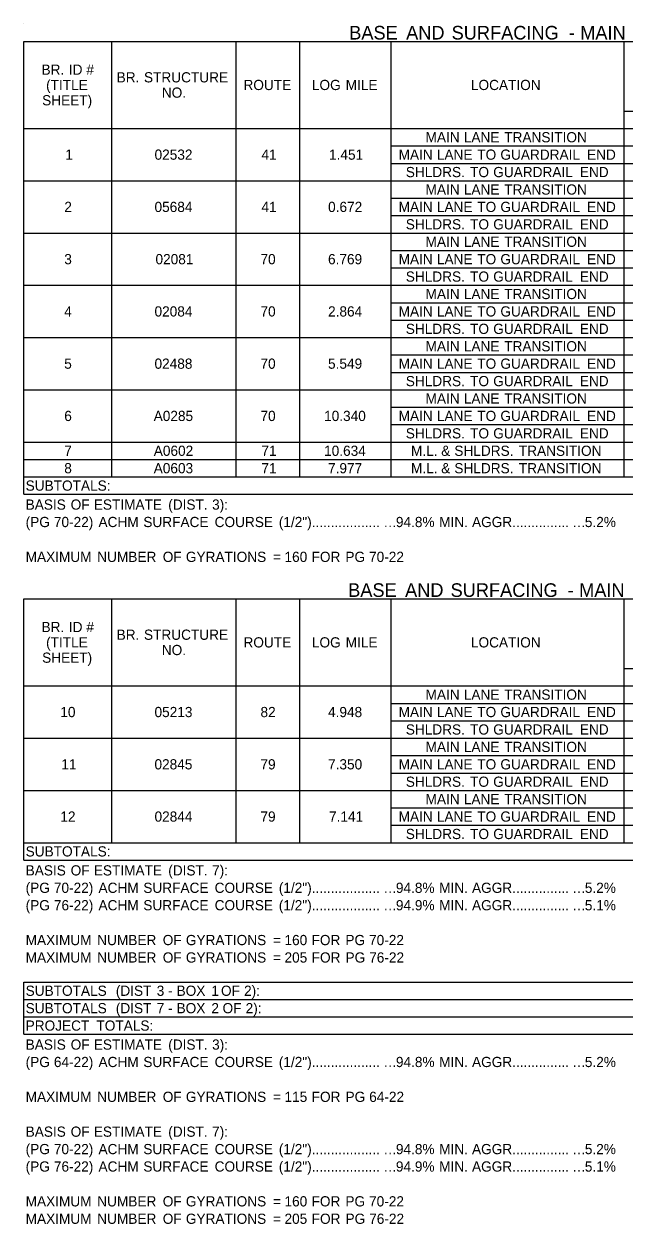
# Model space of a CAD drawing. Extents: x 544478 to 1930787, y -1948294 to 596640.
# Drawn here: x 548362 to 548715, y -1946874 to -1946169 of the extents above; entities that cross this region are included whole.
import ezdxf

# ---------------------------------------------------------------- set-up
doc = ezdxf.new("R2010")
doc.units = 0
doc.layers.add('Default', color=7, linetype='Continuous')

msp = doc.modelspace()

# ---------------------------------------------------------------- linework, layer by layer
at = {"layer": 'Default'}
for p, q in [((548361.91, -1946168.6), (548361.91, -1946168.6)), ((548361.91, -1946178.84), (549135.09, -1946178.84)), ((548361.91, -1946178.84), (549135.09, -1946178.84)), ((548361.91, -1946445.02), (548361.91, -1946178.84)), ((548413.59, -1946230.03), (548413.59, -1946178.84)), ((548486.71, -1946230.03), (548486.71, -1946178.84)), ((548524.25, -1946230.03), (548524.25, -1946178.84)), ((548577.88, -1946434.78), (548577.88, -1946178.84)), ((548714.86, -1946434.78), (548714.86, -1946178.84)), ((548714.86, -1946219.79), (548776.78, -1946219.79)), ((548714.86, -1946219.79), (548836.25, -1946219.79)), ((548361.91, -1946230.03), (549135.09, -1946230.03)), ((548413.59, -1946434.78), (548413.59, -1946230.03)), ((548486.71, -1946434.78), (548486.71, -1946230.03)), ((548524.25, -1946434.78), (548524.25, -1946230.03)), ((548577.88, -1946240.27), (549135.09, -1946240.27)), ((548577.88, -1946250.5), (548714.86, -1946250.5)), ((548577.88, -1946250.5), (549135.09, -1946250.5)), ((548361.91, -1946260.74), (549135.09, -1946260.74)), ((548577.88, -1946270.98), (549135.09, -1946270.98)), ((548577.88, -1946281.22), (548714.86, -1946281.22)), ((548577.88, -1946281.22), (549135.09, -1946281.22)), ((548361.91, -1946291.45), (549036.61, -1946291.45)), ((548714.86, -1946291.45), (548836.25, -1946291.45)), ((548577.88, -1946301.69), (549135.09, -1946301.69)), ((548577.88, -1946311.93), (548714.86, -1946311.93)), ((548577.88, -1946311.93), (549135.09, -1946311.93)), ((548361.91, -1946322.17), (549135.09, -1946322.17)), ((548577.88, -1946332.4), (549135.09, -1946332.4)), ((548577.88, -1946342.64), (548714.86, -1946342.64)), ((548577.88, -1946342.64), (549135.09, -1946342.64)), ((548361.91, -1946352.88), (549036.61, -1946352.88)), ((548714.86, -1946352.88), (548836.25, -1946352.88)), ((548577.88, -1946363.12), (549135.09, -1946363.12)), ((548577.88, -1946373.35), (548714.86, -1946373.35)), ((548577.88, -1946373.35), (549135.09, -1946373.35)), ((548361.91, -1946383.59), (549135.09, -1946383.59)), ((548577.88, -1946393.83), (549135.09, -1946393.83)), ((548577.88, -1946404.07), (548714.86, -1946404.07)), ((548577.88, -1946404.07), (549135.09, -1946404.07)), ((548361.91, -1946414.3), (549135.09, -1946414.3)), ((548577.88, -1946414.3), (549135.09, -1946414.3)), ((548361.91, -1946424.54), (548524.25, -1946424.54)), ((548524.25, -1946424.54), (549135.09, -1946424.54)), ((548361.91, -1946434.78), (549135.09, -1946434.78)), ((548361.91, -1946445.02), (549135.09, -1946445.02)), ((548361.91, -1946506.44), (549135.09, -1946506.44)), ((548361.91, -1946506.44), (549135.09, -1946506.44)), ((548361.91, -1946660), (548361.91, -1946506.44)), ((548413.59, -1946557.63), (548413.59, -1946506.44)), ((548486.71, -1946557.63), (548486.71, -1946506.44)), ((548524.25, -1946557.63), (548524.25, -1946506.44)), ((548577.88, -1946649.77), (548577.88, -1946506.44)), ((548714.86, -1946649.77), (548714.86, -1946506.44)), ((548714.86, -1946547.39), (548776.78, -1946547.39)), ((548714.86, -1946547.39), (548836.25, -1946547.39)), ((548361.91, -1946557.63), (549135.09, -1946557.63)), ((548413.59, -1946649.77), (548413.59, -1946557.63)), ((548486.71, -1946649.77), (548486.71, -1946557.63)), ((548524.25, -1946649.77), (548524.25, -1946557.63)), ((548577.88, -1946567.87), (549135.09, -1946567.87)), ((548577.88, -1946578.1), (548836.25, -1946578.1)), ((548577.88, -1946578.1), (548776.78, -1946578.1)), ((548361.91, -1946588.34), (549135.09, -1946588.34)), ((548577.88, -1946588.34), (548714.86, -1946588.34)), ((548577.88, -1946598.58), (549135.09, -1946598.58)), ((548577.88, -1946608.82), (548836.25, -1946608.82)), ((548577.88, -1946608.82), (548776.78, -1946608.82)), ((548361.91, -1946619.05), (549135.09, -1946619.05)), ((548577.88, -1946629.29), (549135.09, -1946629.29)), ((548577.88, -1946639.53), (548836.25, -1946639.53)), ((548577.88, -1946639.53), (548776.78, -1946639.53)), ((548361.91, -1946649.77), (549135.09, -1946649.77)), ((548361.91, -1946660), (549135.09, -1946660)), ((548361.91, -1946731.67), (549135.09, -1946731.67)), ((548361.91, -1946731.67), (549135.09, -1946731.67)), ((548361.91, -1946762.38), (548361.91, -1946731.67)), ((548361.91, -1946741.9), (549135.09, -1946741.9)), ((548361.91, -1946752.14), (549135.09, -1946752.14)), ((548361.91, -1946762.38), (549135.09, -1946762.38))]:
    msp.add_line(p, q, dxfattribs=at)

# ---------------------------------------------------------------- texts
for s, height, p in [('BASE', 8, (548553.22, -1946177.72)), (' AND', 8, (548583.73, -1946177.72)), (' SURFACING', 8, (548610.49, -1946177.72)), (' MAIN', 8, (548686.12, -1946177.72)), (' -', 8, (548679.37, -1946177.72)), ('BR.', 6, (548372.23, -1946198.43)), (' ID', 6, (548386.09, -1946198.43)), (' #', 6, (548396.38, -1946198.43)), ('BR.', 6, (548416.41, -1946202.93)), (' STRUCTURE', 6, (548430.27, -1946202.93)), ('(TITLE', 6, (548374.92, -1946207.43)), ('NO.', 6, (548442.99, -1946211.93)), ('ROUTE', 6, (548491.02, -1946207.43)), ('LOG', 6, (548531.27, -1946207.43)), (' MILE', 6, (548548.92, -1946207.43)), ('LOCATION', 6, (548624.82, -1946207.43)), ('SHEET)', 6, (548372.59, -1946216.43)), ('MAIN', 6, (548598.14, -1946238.15)), (' LANE', 6, (548618.41, -1946238.15)), (' TRANSITION', 6, (548642.19, -1946238.15)), ('1', 6, (548386.19, -1946248.38)), ('02532', 6, (548438.72, -1946248.38)), ('41', 6, (548501.59, -1946248.38)), ('1.451', 6, (548541.35, -1946248.38)), ('MAIN', 6, (548582.28, -1946248.38)), (' LANE', 6, (548602.55, -1946248.38)), (' TO', 6, (548626.33, -1946248.38)), (' GUARDRAIL', 6, (548639.93, -1946248.38)), (' END', 6, (548690.88, -1946248.38)), ('SHLDRS.', 6, (548586.5, -1946258.62)), (' TO', 6, (548622.11, -1946258.62)), (' GUARDRAIL', 6, (548635.71, -1946258.62)), (' END', 6, (548686.65, -1946258.62)), ('MAIN', 6, (548598.14, -1946268.86)), (' LANE', 6, (548618.41, -1946268.86)), (' TRANSITION', 6, (548642.19, -1946268.86)), ('2', 6, (548385.64, -1946279.1)), ('05684', 6, (548438.7, -1946279.1)), ('41', 6, (548501.59, -1946279.1)), ('0.672', 6, (548540.8, -1946279.1)), ('MAIN', 6, (548582.28, -1946279.1)), (' LANE', 6, (548602.55, -1946279.1)), (' TO', 6, (548626.33, -1946279.1)), (' GUARDRAIL', 6, (548639.93, -1946279.1)), (' END', 6, (548690.88, -1946279.1)), ('SHLDRS.', 6, (548586.5, -1946289.33)), (' TO', 6, (548622.11, -1946289.33)), (' GUARDRAIL', 6, (548635.71, -1946289.33)), (' END', 6, (548686.65, -1946289.33)), ('MAIN', 6, (548598.14, -1946299.57)), (' LANE', 6, (548618.41, -1946299.57)), (' TRANSITION', 6, (548642.19, -1946299.57)), ('3', 6, (548385.61, -1946309.81)), ('02081', 6, (548439.27, -1946309.81)), ('70', 6, (548501.02, -1946309.81)), ('6.769', 6, (548540.76, -1946309.81)), ('MAIN', 6, (548582.28, -1946309.81)), (' LANE', 6, (548602.55, -1946309.81)), (' TO', 6, (548626.33, -1946309.81)), (' GUARDRAIL', 6, (548639.93, -1946309.81)), (' END', 6, (548690.88, -1946309.81)), ('SHLDRS.', 6, (548586.5, -1946320.05)), (' TO', 6, (548622.11, -1946320.05)), (' GUARDRAIL', 6, (548635.71, -1946320.05)), (' END', 6, (548686.65, -1946320.05)), ('MAIN', 6, (548598.14, -1946330.28)), (' LANE', 6, (548618.41, -1946330.28)), (' TRANSITION', 6, (548642.19, -1946330.28)), ('4', 6, (548385.62, -1946340.52)), ('02084', 6, (548438.7, -1946340.52)), ('70', 6, (548501.02, -1946340.52)), ('2.864', 6, (548540.78, -1946340.52)), ('MAIN', 6, (548582.28, -1946340.52)), (' LANE', 6, (548602.55, -1946340.52)), (' TO', 6, (548626.33, -1946340.52)), (' GUARDRAIL', 6, (548639.93, -1946340.52)), (' END', 6, (548690.88, -1946340.52)), ('SHLDRS.', 6, (548586.5, -1946350.76)), (' TO', 6, (548622.11, -1946350.76)), (' GUARDRAIL', 6, (548635.71, -1946350.76)), (' END', 6, (548686.65, -1946350.76)), ('MAIN', 6, (548598.14, -1946361)), (' LANE', 6, (548618.41, -1946361)), (' TRANSITION', 6, (548642.19, -1946361)), ('5', 6, (548385.59, -1946371.23)), ('02488', 6, (548438.69, -1946371.23)), ('70', 6, (548501.02, -1946371.23)), ('5.549', 6, (548540.76, -1946371.23)), ('MAIN', 6, (548582.28, -1946371.23)), (' LANE', 6, (548602.55, -1946371.23)), (' TO', 6, (548626.33, -1946371.23)), (' GUARDRAIL', 6, (548639.93, -1946371.23)), (' END', 6, (548690.88, -1946371.23)), ('SHLDRS.', 6, (548586.5, -1946381.47)), (' TO', 6, (548622.11, -1946381.47)), (' GUARDRAIL', 6, (548635.71, -1946381.47)), (' END', 6, (548686.65, -1946381.47)), ('MAIN', 6, (548598.14, -1946391.71)), (' LANE', 6, (548618.41, -1946391.71)), (' TRANSITION', 6, (548642.19, -1946391.71)), ('6', 6, (548385.61, -1946401.95)), ('A0285', 6, (548438.2, -1946401.95)), ('70', 6, (548501.02, -1946401.95)), ('10.340', 6, (548538.45, -1946401.95)), ('MAIN', 6, (548582.28, -1946401.95)), (' LANE', 6, (548602.55, -1946401.95)), (' TO', 6, (548626.33, -1946401.95)), (' GUARDRAIL', 6, (548639.93, -1946401.95)), (' END', 6, (548690.88, -1946401.95)), ('SHLDRS.', 6, (548586.5, -1946412.18)), (' TO', 6, (548622.11, -1946412.18)), (' GUARDRAIL', 6, (548635.71, -1946412.18)), (' END', 6, (548686.65, -1946412.18)), ('7', 6, (548385.61, -1946422.42)), ('A0602', 6, (548438.26, -1946422.42)), ('71', 6, (548501.59, -1946422.42)), ('10.634', 6, (548538.45, -1946422.42)), ('M.L.', 6, (548589.55, -1946422.42)), (' &', 6, (548605.11, -1946422.42)), (' SHLDRS.', 6, (548612.84, -1946422.42)), (' TRANSITION', 6, (548650.78, -1946422.42)), ('8', 6, (548385.61, -1946432.66)), ('A0603', 6, (548438.22, -1946432.66)), ('71', 6, (548501.59, -1946432.66)), ('7.977', 6, (548540.77, -1946432.66)), ('M.L.', 6, (548589.55, -1946432.66)), (' &', 6, (548605.11, -1946432.66)), (' SHLDRS.', 6, (548612.84, -1946432.66)), (' TRANSITION', 6, (548650.78, -1946432.66)), ('SUBTOTALS:', 6, (548362.89, -1946442.9)), ('BASIS', 6, (548362.89, -1946454.05)), (' OF', 6, (548387.15, -1946454.05)), (' ESTIMATE', 6, (548400.74, -1946454.05)), (' (DIST.', 6, (548444.54, -1946454.05)), (' 3):', 6, (548470.35, -1946454.05)), ('(PG', 6, (548362.89, -1946464.29)), (' 70-22)', 6, (548377.27, -1946464.29)), (' ACHM', 6, (548403.51, -1946464.29)), (' SURFACE', 6, (548429.89, -1946464.29)), (' COURSE', 6, (548471.84, -1946464.29)), (' (1/2")..................', 6, (548509.59, -1946464.29)), ('94.8%', 6, (548580.69, -1946464.29)), (' MIN.', 6, (548603.93, -1946464.29)), (' AGGR...............', 6, (548623.22, -1946464.29)), ('5.2%', 6, (548691.82, -1946464.29)), ('…', 6, (548573.29, -1946464.29)), ('…', 6, (548684.42, -1946464.29)), ('MAXIMUM', 6, (548362.89, -1946484.77)), (' NUMBER', 6, (548402.77, -1946484.77)), (' OF', 6, (548441.32, -1946484.77)), (' GYRATIONS', 6, (548454.91, -1946484.77)), (' =', 6, (548506.18, -1946484.77)), (' 160', 6, (548512.93, -1946484.77)), (' FOR', 6, (548528.84, -1946484.77)), (' PG', 6, (548548.75, -1946484.77)), (' 70-22', 6, (548562.67, -1946484.77)), ('BASE', 8, (548552.6, -1946505.32)), (' AND', 8, (548583.11, -1946505.32)), (' SURFACING', 8, (548609.88, -1946505.32)), (' -', 8, (548678.75, -1946505.32)), (' MAIN', 8, (548685.5, -1946505.32)), ('BR.', 6, (548372.23, -1946526.03)), (' ID', 6, (548386.09, -1946526.03)), (' #', 6, (548396.38, -1946526.03)), ('(TITLE', 6, (548374.92, -1946535.03)), ('BR.', 6, (548416.41, -1946530.53)), (' STRUCTURE', 6, (548430.27, -1946530.53)), ('ROUTE', 6, (548491.02, -1946535.03)), ('LOG', 6, (548531.27, -1946535.03)), (' MILE', 6, (548548.92, -1946535.03)), ('LOCATION', 6, (548624.82, -1946535.03)), ('SHEET)', 6, (548372.59, -1946544.03)), ('NO.', 6, (548442.99, -1946539.53)), ('MAIN', 6, (548598.14, -1946565.75)), (' LANE', 6, (548618.41, -1946565.75)), (' TRANSITION', 6, (548642.19, -1946565.75)), ('10', 6, (548383.29, -1946575.98)), ('05213', 6, (548438.69, -1946575.98)), ('82', 6, (548501.04, -1946575.98)), ('4.948', 6, (548540.76, -1946575.98)), ('MAIN', 6, (548582.28, -1946575.98)), (' LANE', 6, (548602.55, -1946575.98)), (' TO', 6, (548626.33, -1946575.98)), (' GUARDRAIL', 6, (548639.93, -1946575.98)), (' END', 6, (548690.88, -1946575.98)), ('SHLDRS.', 6, (548586.5, -1946586.22)), (' TO', 6, (548622.11, -1946586.22)), (' GUARDRAIL', 6, (548635.71, -1946586.22)), (' END', 6, (548686.65, -1946586.22)), ('MAIN', 6, (548598.14, -1946596.46)), (' LANE', 6, (548618.41, -1946596.46)), (' TRANSITION', 6, (548642.19, -1946596.46)), ('11', 6, (548383.86, -1946606.7)), ('02845', 6, (548438.67, -1946606.7)), ('79', 6, (548501.01, -1946606.7)), ('7.350', 6, (548540.78, -1946606.7)), ('MAIN', 6, (548582.28, -1946606.7)), (' LANE', 6, (548602.55, -1946606.7)), (' TO', 6, (548626.33, -1946606.7)), (' GUARDRAIL', 6, (548639.93, -1946606.7)), (' END', 6, (548690.88, -1946606.7)), ('SHLDRS.', 6, (548586.5, -1946616.93)), (' TO', 6, (548622.11, -1946616.93)), (' GUARDRAIL', 6, (548635.71, -1946616.93)), (' END', 6, (548686.65, -1946616.93)), ('MAIN', 6, (548598.14, -1946627.17)), (' LANE', 6, (548618.41, -1946627.17)), (' TRANSITION', 6, (548642.19, -1946627.17)), ('12', 6, (548383.31, -1946637.41)), ('02844', 6, (548438.7, -1946637.41)), ('79', 6, (548501.01, -1946637.41)), ('7.141', 6, (548541.35, -1946637.41)), ('MAIN', 6, (548582.28, -1946637.41)), (' LANE', 6, (548602.55, -1946637.41)), (' TO', 6, (548626.33, -1946637.41)), (' GUARDRAIL', 6, (548639.93, -1946637.41)), (' END', 6, (548690.88, -1946637.41)), ('SHLDRS.', 6, (548586.5, -1946647.65)), (' TO', 6, (548622.11, -1946647.65)), (' GUARDRAIL', 6, (548635.71, -1946647.65)), (' END', 6, (548686.65, -1946647.65)), ('SUBTOTALS:', 6, (548362.89, -1946657.88)), ('BASIS', 6, (548362.89, -1946669.04)), (' OF', 6, (548387.15, -1946669.04)), (' ESTIMATE', 6, (548400.74, -1946669.04)), (' (DIST.', 6, (548444.54, -1946669.04)), (' 7):', 6, (548470.35, -1946669.04)), ('(PG', 6, (548362.89, -1946679.28)), (' 70-22)', 6, (548377.27, -1946679.28)), (' ACHM', 6, (548403.51, -1946679.28)), (' SURFACE', 6, (548429.89, -1946679.28)), (' COURSE', 6, (548471.84, -1946679.28)), (' (1/2")..................', 6, (548509.59, -1946679.28)), ('…', 6, (548573.29, -1946679.28)), ('94.8%', 6, (548580.69, -1946679.28)), (' MIN.', 6, (548603.93, -1946679.28)), (' AGGR...............', 6, (548623.22, -1946679.28)), ('…', 6, (548684.42, -1946679.28)), ('5.2%', 6, (548691.82, -1946679.28)), ('(PG', 6, (548362.89, -1946689.52)), (' 76-22)', 6, (548377.27, -1946689.52)), (' ACHM', 6, (548403.51, -1946689.52)), (' SURFACE', 6, (548429.89, -1946689.52)), (' COURSE', 6, (548471.84, -1946689.52)), (' (1/2")..................', 6, (548509.59, -1946689.52)), ('94.9%', 6, (548580.69, -1946689.52)), (' MIN.', 6, (548603.93, -1946689.52)), (' AGGR...............', 6, (548623.22, -1946689.52)), ('5.1%', 6, (548691.82, -1946689.52)), ('…', 6, (548573.29, -1946689.52)), ('…', 6, (548684.42, -1946689.52)), ('MAXIMUM', 6, (548362.89, -1946709.99)), (' NUMBER', 6, (548402.77, -1946709.99)), (' OF', 6, (548441.32, -1946709.99)), (' GYRATIONS', 6, (548454.91, -1946709.99)), (' =', 6, (548506.18, -1946709.99)), (' 160', 6, (548512.93, -1946709.99)), (' FOR', 6, (548528.84, -1946709.99)), (' PG', 6, (548548.75, -1946709.99)), (' 70-22', 6, (548562.67, -1946709.99)), ('MAXIMUM', 6, (548362.89, -1946720.23)), (' NUMBER', 6, (548402.77, -1946720.23)), (' OF', 6, (548441.32, -1946720.23)), (' GYRATIONS', 6, (548454.91, -1946720.23)), (' 205', 6, (548512.93, -1946720.23)), (' FOR', 6, (548528.91, -1946720.23)), (' PG', 6, (548548.82, -1946720.23)), (' 76-22', 6, (548562.74, -1946720.23)), (' =', 6, (548506.18, -1946720.23)), ('SUBTOTALS', 6, (548362.89, -1946739.78)), (' (DIST', 6, (548413.71, -1946739.78)), (' 3', 6, (548437.76, -1946739.78)), (' BOX', 6, (548449.44, -1946739.78)), (' 1', 6, (548469.93, -1946739.78)), (' OF', 6, (548475.56, -1946739.78)), (' 2):', 6, (548489.14, -1946739.78)), (' -', 6, (548444.38, -1946739.78)), ('SUBTOTALS', 6, (548362.89, -1946750.02)), (' (DIST', 6, (548413.71, -1946750.02)), (' 7', 6, (548437.76, -1946750.02)), (' -', 6, (548444.37, -1946750.02)), (' BOX', 6, (548449.43, -1946750.02)), (' 2', 6, (548469.92, -1946750.02)), (' OF', 6, (548476.49, -1946750.02)), (' 2):', 6, (548490.07, -1946750.02)), ('PROJECT', 6, (548362.89, -1946760.26)), (' TOTALS:', 6, (548402.31, -1946760.26)), ('BASIS', 6, (548362.89, -1946771.42)), (' OF', 6, (548387.15, -1946771.42)), (' ESTIMATE', 6, (548400.74, -1946771.42)), (' (DIST.', 6, (548444.54, -1946771.42)), (' 3):', 6, (548470.35, -1946771.42)), ('(PG', 6, (548362.89, -1946781.65)), (' 64-22)', 6, (548377.27, -1946781.65)), (' ACHM', 6, (548403.51, -1946781.65)), (' SURFACE', 6, (548429.89, -1946781.65)), (' COURSE', 6, (548471.84, -1946781.65)), (' (1/2")..................', 6, (548509.59, -1946781.65)), ('94.8%', 6, (548580.69, -1946781.65)), (' MIN.', 6, (548603.93, -1946781.65)), (' AGGR...............', 6, (548623.22, -1946781.65)), ('5.2%', 6, (548691.82, -1946781.65)), ('…', 6, (548573.29, -1946781.65)), ('…', 6, (548684.42, -1946781.65)), ('MAXIMUM', 6, (548362.89, -1946802.13)), (' NUMBER', 6, (548402.77, -1946802.13)), (' OF', 6, (548441.32, -1946802.13)), (' GYRATIONS', 6, (548454.91, -1946802.13)), (' =', 6, (548506.18, -1946802.13)), (' 115', 6, (548512.93, -1946802.13)), (' FOR', 6, (548528.91, -1946802.13)), (' PG', 6, (548548.82, -1946802.13)), (' 64-22', 6, (548562.74, -1946802.13)), ('BASIS', 6, (548362.89, -1946822.6)), (' OF', 6, (548387.15, -1946822.6)), (' ESTIMATE', 6, (548400.74, -1946822.6)), (' (DIST.', 6, (548444.54, -1946822.6)), (' 7):', 6, (548470.35, -1946822.6)), ('(PG', 6, (548362.89, -1946832.84)), (' 70-22)', 6, (548377.27, -1946832.84)), (' ACHM', 6, (548403.51, -1946832.84)), (' SURFACE', 6, (548429.89, -1946832.84)), (' COURSE', 6, (548471.84, -1946832.84)), (' (1/2")..................', 6, (548509.59, -1946832.84)), ('94.8%', 6, (548580.69, -1946832.84)), (' MIN.', 6, (548603.93, -1946832.84)), (' AGGR...............', 6, (548623.22, -1946832.84)), ('5.2%', 6, (548691.82, -1946832.84)), ('…', 6, (548573.29, -1946832.84)), ('…', 6, (548684.42, -1946832.84)), ('(PG', 6, (548362.89, -1946843.08)), (' 76-22)', 6, (548377.27, -1946843.08)), (' ACHM', 6, (548403.51, -1946843.08)), (' SURFACE', 6, (548429.89, -1946843.08)), (' COURSE', 6, (548471.84, -1946843.08)), (' (1/2")..................', 6, (548509.59, -1946843.08)), ('94.9%', 6, (548580.69, -1946843.08)), (' MIN.', 6, (548603.93, -1946843.08)), (' AGGR...............', 6, (548623.22, -1946843.08)), ('5.1%', 6, (548691.82, -1946843.08)), ('…', 6, (548573.29, -1946843.08)), ('…', 6, (548684.42, -1946843.08)), ('MAXIMUM', 6, (548362.89, -1946863.55)), (' NUMBER', 6, (548402.77, -1946863.55)), (' OF', 6, (548441.32, -1946863.55)), (' GYRATIONS', 6, (548454.91, -1946863.55)), (' =', 6, (548506.18, -1946863.55)), (' 160', 6, (548512.93, -1946863.55)), (' FOR', 6, (548528.84, -1946863.55)), (' PG', 6, (548548.75, -1946863.55)), (' 70-22', 6, (548562.67, -1946863.55)), ('MAXIMUM', 6, (548362.89, -1946873.79)), (' NUMBER', 6, (548402.77, -1946873.79)), (' OF', 6, (548441.32, -1946873.79)), (' GYRATIONS', 6, (548454.91, -1946873.79)), (' =', 6, (548506.18, -1946873.79)), (' 205', 6, (548512.93, -1946873.79)), (' FOR', 6, (548528.91, -1946873.79)), (' PG', 6, (548548.82, -1946873.79)), (' 76-22', 6, (548562.74, -1946873.79))]:
    msp.add_text(s, height=height, dxfattribs=at).set_placement(p)

doc.saveas('drawing.dxf')
